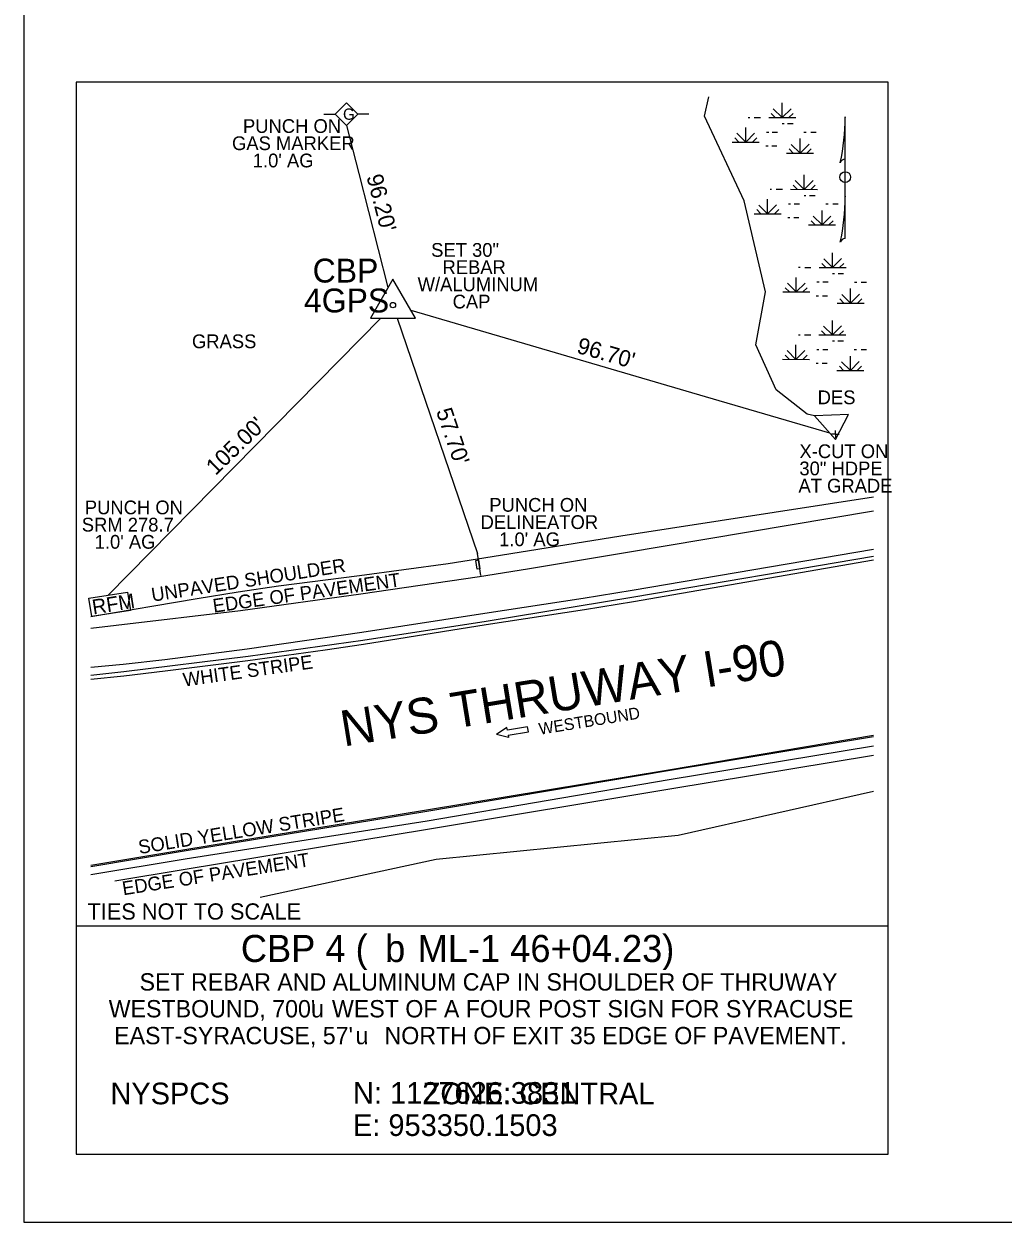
# Model space of a CAD drawing. Extents: x 953375 to 953970, y 1125154 to 1125656.
# Drawn here: x 953374.9 to 953579.9, y 1125154 to 1125404.8 of the extents above; entities that cross this region are included whole.
import ezdxf

# ---------------------------------------------------------------- set-up
doc = ezdxf.new("R2010")
doc.units = 0
for name, color, linetype in [('CB', 7, 'Continuous'), ('CBP', 7, 'Continuous'), ('CBP_C', 7, 'Continuous'), ('CBS_C', 7, 'Continuous'), ('CBT', 7, 'Continuous'), ('Default', 7, 'Continuous'), ('DES', 7, 'Continuous'), ('DES_C', 7, 'Continuous'), ('DINV', 7, 'Continuous'), ('LUKP_C', 7, 'Continuous'), ('NNA_P', 7, 'Continuous'), ('PE', 7, 'Continuous'), ('PE_C', 7, 'Continuous'), ('PET', 7, 'Continuous'), ('PSU', 7, 'Continuous'), ('PSU_C', 7, 'Continuous'), ('RC_C', 7, 'Continuous'), ('RRS', 7, 'Continuous'), ('SDEL', 7, 'Continuous'), ('SRM', 7, 'Continuous'), ('STSEW', 7, 'Continuous'), ('STSEW_I', 7, 'Continuous'), ('STSEY', 7, 'Continuous'), ('STSEY_C', 7, 'Continuous')]:
    doc.layers.add(name, color=color, linetype=linetype)

# ---------------------------------------------------------------- blocks, each defined once
blk = doc.blocks.new('NNAM')
at = {"layer": 'NNA_P'}
for p, q in [((0, 0.0147), (0, 0.0501)), ((0, 0.0496), (0, 0.0496)), ((0, 0.0496), (0, 0.0496)), ((0, -0.0004), (0, 0.0147)), ((0, -0.0168), (0, -0.0004)), ((0, -0.0166), (0, -0.0168)), ((0, -0.0172), (0, -0.0168)), ((0, -0.0518), (0, -0.0172))]:
    blk.add_line(p, q, dxfattribs=at)
blk.add_circle((0, -0.0003), 0.00455, dxfattribs=at)
for centre, radius, start, end in [((-0.1834, 0.0501), 0.1834, 347.8839, 359.8678), ((0.1834, 0.0501), 0.1834, 179.9909, 180.1322), ((0, 0.0105), 0.00425, 90.435, 165.5809), ((-0.1834, -0.0164), 0.1834, 347.8839, 359.8678), ((0.1834, -0.0164), 0.1834, 179.9909, 180.1322), ((-0.1834, -0.0164), 0.1834, 359.9196, 0.009), ((0, -0.056), 0.00424, 90.0107, 164.1061)]:
    blk.add_arc(centre, radius, start, end, dxfattribs=at)

msp = doc.modelspace()

# ---------------------------------------------------------------- linework, layer by layer
at = {"layer": 'CB'}
msp.add_line((953385.84, 1125215.99), (953555.84, 1125215.99), dxfattribs=at)
msp.add_lwpolyline([(953555.84, 1125168.2), (953555.84, 1125392.66), (953385.84, 1125392.66), (953385.84, 1125168.2)], close=True, dxfattribs=at)
at = {"layer": 'CBP'}
for points in [[(953452.16, 1125351.43), (953447.43, 1125343.25)], [(953456.88, 1125343.25), (953452.16, 1125351.43)], [(953447.43, 1125343.25), (953456.88, 1125343.25)]]:
    msp.add_lwpolyline(points, dxfattribs=at)
msp.add_circle((953452.16, 1125345.97), 0.564, dxfattribs=at)
at = {"layer": 'CBT'}
for p, q in [((953442.42, 1125383.61), (953445.01, 1125373.56)), ((953451.12, 1125349.63), (953451.12, 1125349.63)), ((953455.95, 1125344.86), (953455.95, 1125344.86)), ((953449.65, 1125343.25), (953449.65, 1125343.25)), ((953453.06, 1125343.25), (953469.83, 1125293.99)), ((953543.64, 1125319.15), (953517.6, 1125326.79)), ((953392.55, 1125285.24), (953392.55, 1125285.24))]:
    msp.add_line(p, q, dxfattribs=at)
for points in [[(953445.01, 1125373.56), (953451.12, 1125349.63)], [(953517.6, 1125326.78), (953455.95, 1125344.86)], [(953392.55, 1125285.24), (953449.65, 1125343.25)]]:
    msp.add_lwpolyline(points, dxfattribs=at)
at = {"layer": 'Default'}
msp.add_lwpolyline([(953374.91, 1125153.95), (953970.07, 1125153.95), (953970.07, 1125655.74), (953374.91, 1125655.74)], close=True, dxfattribs=at)
at = {"layer": 'DES'}
msp.add_lwpolyline([(953540.43, 1125322.79), (953544.83, 1125317.81), (953547.52, 1125323.03), (953540.43, 1125322.79)], dxfattribs=at)
at = {"layer": 'DINV'}
for q in [(953544.01, 1125318.93), (953544.79, 1125319.72), (953545.58, 1125318.93), (953544.79, 1125318.15)]:
    msp.add_line((953544.79, 1125318.93), q, dxfattribs=at)
at = {"layer": 'PE'}
for p, q in [((953440.06, 1125385.97), (953442.41, 1125388.33)), ((953442.41, 1125388.33), (953444.78, 1125385.97)), ((953533.64, 1125385.23), (953533.64, 1125388.3)), ((953442.42, 1125383.61), (953440.06, 1125385.97)), ((953444.78, 1125385.97), (953442.42, 1125383.61)), ((953526.51, 1125385.29), (953526.86, 1125385.29)), ((953527.82, 1125385.26), (953529.1, 1125385.26)), ((953530.83, 1125385.26), (953536.48, 1125385.23)), ((953532.21, 1125385.26), (953531.36, 1125386.12)), ((953533.64, 1125385.23), (953531.8, 1125387.07)), ((953533.64, 1125385.23), (953535.52, 1125387.11)), ((953535.08, 1125385.23), (953535.95, 1125386.12)), ((953526.01, 1125380.12), (953526.01, 1125383.18)), ((953533.64, 1125383.98), (953534.05, 1125383.98)), ((953534.78, 1125383.98), (953535.94, 1125383.98)), ((953523.19, 1125380.13), (953528.85, 1125380.12)), ((953524.59, 1125380.13), (953523.72, 1125381.01)), ((953526.01, 1125380.12), (953524.17, 1125381.96)), ((953526.01, 1125380.12), (953527.87, 1125382)), ((953527.43, 1125380.12), (953528.32, 1125381.01)), ((953530.35, 1125382.22), (953530.83, 1125382.22)), ((953531.59, 1125382.22), (953532.67, 1125382.22)), ((953537.4, 1125377.78), (953537.4, 1125380.83)), ((953538.2, 1125382.21), (953538.7, 1125382.21)), ((953539.63, 1125382.18), (953540.76, 1125382.18)), ((953530.21, 1125379.31), (953530.69, 1125379.31)), ((953531.52, 1125379.31), (953532.55, 1125379.31)), ((953534.59, 1125377.79), (953540.24, 1125377.78)), ((953535.98, 1125377.79), (953535.12, 1125378.67)), ((953537.4, 1125377.78), (953535.56, 1125379.62)), ((953537.4, 1125377.78), (953539.27, 1125379.66)), ((953538.82, 1125377.78), (953539.71, 1125378.67)), ((953538.24, 1125370.21), (953538.24, 1125373.27)), ((953531.11, 1125370.26), (953531.45, 1125370.26)), ((953532.42, 1125370.23), (953533.7, 1125370.23)), ((953535.42, 1125370.23), (953541.08, 1125370.21)), ((953536.8, 1125370.23), (953535.95, 1125371.1)), ((953538.24, 1125370.21), (953536.4, 1125372.05)), ((953538.24, 1125370.21), (953540.12, 1125372.09)), ((953539.67, 1125370.21), (953540.55, 1125371.1)), ((953530.6, 1125365.09), (953530.6, 1125368.16)), ((953538.24, 1125368.95), (953538.64, 1125368.95)), ((953539.38, 1125368.95), (953540.54, 1125368.95)), ((953527.79, 1125365.11), (953533.45, 1125365.09)), ((953529.18, 1125365.11), (953528.32, 1125365.99)), ((953530.6, 1125365.09), (953528.77, 1125366.93)), ((953530.6, 1125365.09), (953532.47, 1125366.97)), ((953532.03, 1125365.09), (953532.92, 1125365.99)), ((953534.95, 1125367.2), (953535.42, 1125367.2)), ((953536.19, 1125367.2), (953537.26, 1125367.2)), ((953542, 1125362.75), (953542, 1125365.8)), ((953542.79, 1125367.18), (953543.29, 1125367.18)), ((953544.23, 1125367.16), (953545.36, 1125367.16)), ((953534.81, 1125364.29), (953535.29, 1125364.29)), ((953536.12, 1125364.29), (953537.15, 1125364.29)), ((953539.19, 1125362.77), (953544.84, 1125362.75)), ((953540.58, 1125362.77), (953539.71, 1125363.65)), ((953542, 1125362.75), (953540.16, 1125364.59)), ((953542, 1125362.75), (953543.87, 1125364.63)), ((953543.42, 1125362.75), (953544.31, 1125363.65)), ((953544.22, 1125353.83), (953542.38, 1125355.67)), ((953544.22, 1125353.83), (953544.22, 1125356.9)), ((953544.22, 1125353.83), (953546.1, 1125355.71)), ((953537.09, 1125353.89), (953537.44, 1125353.89)), ((953538.4, 1125353.86), (953539.68, 1125353.86)), ((953541.41, 1125353.86), (953547.06, 1125353.83)), ((953542.79, 1125353.86), (953541.94, 1125354.72)), ((953544.22, 1125352.58), (953544.63, 1125352.58)), ((953545.36, 1125352.58), (953546.52, 1125352.58)), ((953545.66, 1125353.83), (953546.53, 1125354.72)), ((953536.59, 1125348.72), (953534.75, 1125350.56)), ((953536.59, 1125348.72), (953536.59, 1125351.78)), ((953536.59, 1125348.72), (953538.46, 1125350.6)), ((953540.93, 1125350.82), (953541.41, 1125350.82)), ((953542.17, 1125350.82), (953543.25, 1125350.82)), ((953548.78, 1125350.81), (953549.28, 1125350.81)), ((953550.21, 1125350.78), (953551.34, 1125350.78)), ((953533.77, 1125348.73), (953539.43, 1125348.72)), ((953535.17, 1125348.73), (953534.3, 1125349.61)), ((953538.01, 1125348.72), (953538.9, 1125349.61)), ((953540.8, 1125347.91), (953541.27, 1125347.91)), ((953542.1, 1125347.91), (953543.14, 1125347.91)), ((953547.98, 1125346.38), (953546.14, 1125348.22)), ((953547.98, 1125346.38), (953547.98, 1125349.43)), ((953547.98, 1125346.38), (953549.85, 1125348.26)), ((953545.17, 1125346.39), (953550.82, 1125346.38)), ((953546.56, 1125346.39), (953545.7, 1125347.27)), ((953549.4, 1125346.38), (953550.3, 1125347.27)), ((953544.17, 1125339.72), (953544.17, 1125342.78)), ((953542.74, 1125339.74), (953541.89, 1125340.61)), ((953544.17, 1125339.72), (953542.33, 1125341.55)), ((953544.17, 1125339.72), (953546.05, 1125341.6)), ((953545.61, 1125339.72), (953546.49, 1125340.61)), ((953536.54, 1125334.6), (953536.54, 1125337.67)), ((953537.04, 1125339.77), (953537.39, 1125339.77)), ((953538.35, 1125339.74), (953539.63, 1125339.74)), ((953541.36, 1125339.74), (953547.01, 1125339.72)), ((953544.17, 1125338.46), (953544.58, 1125338.46)), ((953545.32, 1125338.46), (953546.47, 1125338.46)), ((953535.12, 1125334.62), (953534.26, 1125335.5)), ((953536.54, 1125334.6), (953534.7, 1125336.44)), ((953536.54, 1125334.6), (953538.41, 1125336.48)), ((953537.96, 1125334.6), (953538.85, 1125335.5)), ((953540.89, 1125336.71), (953541.36, 1125336.71)), ((953542.13, 1125336.71), (953543.2, 1125336.71)), ((953547.93, 1125332.26), (953547.93, 1125335.31)), ((953548.73, 1125336.69), (953549.23, 1125336.69)), ((953550.16, 1125336.67), (953551.29, 1125336.67)), ((953533.73, 1125334.62), (953539.38, 1125334.6)), ((953540.75, 1125333.8), (953541.22, 1125333.8)), ((953542.06, 1125333.8), (953543.09, 1125333.8)), ((953546.51, 1125332.28), (953545.65, 1125333.16)), ((953547.93, 1125332.26), (953546.1, 1125334.1)), ((953547.93, 1125332.26), (953549.8, 1125334.14)), ((953549.35, 1125332.26), (953550.25, 1125333.16)), ((953545.12, 1125332.28), (953550.78, 1125332.26))]:
    msp.add_line(p, q, dxfattribs=at)
for points in [[(953540.43, 1125322.79), (953538.91, 1125323.1), (953532.36, 1125328.2), (953528.17, 1125337.66), (953530.17, 1125348.77), (953525.72, 1125367.84), (953517.41, 1125385.57), (953518.28, 1125389.61)], [(953437.7, 1125385.97), (953440.06, 1125385.97)], [(953447.14, 1125385.97), (953444.78, 1125385.97)], [(953547.57, 1125323.04), (953547.52, 1125323.03)], [(953552.77, 1125302.79), (953500.43, 1125294.01), (953480.33, 1125290.66), (953470.27, 1125289.07), (953445.43, 1125285.46), (953420.27, 1125281.98), (953394.19, 1125278.85), (953388.92, 1125278.26)], [(953393.96, 1125225.38), (953408.64, 1125227.82), (953459.36, 1125236.23), (953510.15, 1125244.66), (953552.77, 1125251.74)]]:
    msp.add_lwpolyline(points, dxfattribs=at)
at = {"layer": 'PET'}
for points in [[(953552.77, 1125293.34), (953502.59, 1125284.81), (953471.67, 1125279.75), (953445.84, 1125275.73), (953421.87, 1125272.4), (953395.84, 1125269.16), (953388.92, 1125268.42)], [(953388.92, 1125228.39), (953408.44, 1125231.7), (953458.82, 1125239.91), (953509.79, 1125248.51), (953552.77, 1125255.63)]]:
    msp.add_lwpolyline(points, dxfattribs=at)
at = {"layer": 'PSU'}
for points in [[(953552.77, 1125305.74), (953499.84, 1125297.62), (953472.93, 1125293.23), (953463.7, 1125291.82), (953445.19, 1125289.28), (953428.23, 1125287.09), (953419.77, 1125285.87), (953411.2, 1125284.46), (953388.92, 1125280.68)], [(953424.35, 1125222.01), (953461.19, 1125229.97), (953511.9, 1125234.99), (953552.77, 1125244.16)]]:
    msp.add_lwpolyline(points, dxfattribs=at)
at = {"layer": 'RC_C'}
for p, q in [((953476.02, 1125257.52), (953473.83, 1125256.07)), ((953476.11, 1125256.98), (953476.02, 1125257.52)), ((953480.36, 1125257.68), (953476.11, 1125256.98)), ((953480.53, 1125256.62), (953480.36, 1125257.68)), ((953476.37, 1125255.39), (953473.83, 1125256.07)), ((953476.28, 1125255.93), (953480.53, 1125256.62)), ((953476.28, 1125255.93), (953476.37, 1125255.39))]:
    msp.add_line(p, q, dxfattribs=at)
at = {"layer": 'RRS'}
for points in [[(953552.77, 1125294.81), (953502.22, 1125286.18), (953491.97, 1125284.5), (953471.42, 1125281.36), (953445.63, 1125277.39), (953421.64, 1125273.95), (953404.37, 1125271.69), (953395.71, 1125270.72), (953388.92, 1125270.06)], [(953388.92, 1125226.73), (953408.63, 1125230.03), (953459.34, 1125238), (953510.02, 1125246.62), (953552.77, 1125253.66)]]:
    msp.add_lwpolyline(points, dxfattribs=at)
at = {"layer": 'SDEL'}
msp.add_line((953470.57, 1125289.37), (953469.83, 1125293.99), dxfattribs=at)
msp.add_lwpolyline([(953470.05, 1125292.61), (953470.35, 1125290.75), (953469.79, 1125290.65), (953469.49, 1125292.52)], close=True, dxfattribs=at)
at = {"layer": 'SRM'}
msp.add_lwpolyline([(953388.52, 1125284.6), (953396.59, 1125285.87), (953397.19, 1125282.04), (953389.12, 1125280.77)], close=True, dxfattribs=at)
at = {"layer": 'STSEW'}
msp.add_lwpolyline([(953552.77, 1125292.53), (953502.55, 1125283.85), (953492.28, 1125282.17), (953471.69, 1125279.01), (953446.01, 1125274.91), (953437.94, 1125273.72), (953421.79, 1125271.5), (953404.5, 1125269.3), (953395.84, 1125268.29), (953388.92, 1125267.56)], dxfattribs=at)
at = {"layer": 'STSEY'}
msp.add_lwpolyline([(953388.92, 1125228.71), (953408.56, 1125231.95), (953458.79, 1125240.21), (953509.87, 1125248.64), (953552.77, 1125255.92)], dxfattribs=at)

# ---------------------------------------------------------------- block references
at = {"layer": 'Default', "xscale": 250, "yscale": 250}
msp.add_blockref('NNAM', (953546.85, 1125372.85), dxfattribs=at)

# ---------------------------------------------------------------- texts
at = {"layer": 'CBP_C'}
for s, height, rotation, p in [("96.20'", 3.402, 284.6048, (953446.59, 1125372.9)), ("96.70'", 3.402, 343.9823, (953490.45, 1125336.02)), ("105.00'", 3.402, 43.9686, (953415.03, 1125310.18)), ("57.70'", 3.402, 288.7394, (953461.15, 1125323.78)), ('TIES NOT TO SCALE', 3.4016, 359.9999, (953388.21, 1125217.29))]:
    msp.add_text(s, height=height, rotation=rotation, dxfattribs=at).set_placement(p)
for s, height, p in [('CBP', 5.002, (953435.35, 1125350.7)), ('4GPS', 5.002, (953433.53, 1125344.44)), ('CBP 4 (', 5.669, (953420.32, 1125208.41)), ('b', 5.67, (953450.52, 1125208.41)), (' ML-1 46+04.23)', 5.6693, (953455.23, 1125208.41)), ('SET REBAR AND ALUMINUM CAP IN SHOULDER OF THRUWAY ', 3.6284, (953399.11, 1125202.43)), ("WESTBOUND, 700'", 3.6284, (953392.65, 1125196.81)), ('u', 3.63, (953435, 1125196.81)), (' WEST OF A FOUR POST SIGN FOR SYRACUSE', 3.6284, (953438.04, 1125196.81)), ("EAST-SYRACUSE, 57'", 3.6284, (953393.79, 1125191.19)), ('NORTH OF EXIT 35 EDGE OF PAVEMENT.', 3.6284, (953450.4, 1125191.19)), ('u ', 3.628, (953444.33, 1125191.19)), ('NYSPCS                        ZONE: CENTRAL', 4.5355, (953393.01, 1125178.61)), ('N: 1127626.3831', 4.5355, (953443.8, 1125178.72)), ('E: 953350.1503', 4.5355, (953443.8, 1125171.98))]:
    msp.add_text(s, height=height, dxfattribs=at).set_placement(p)
at = {"layer": 'CBS_C'}
for s, p in [('PUNCH ON', (953420.76, 1125382.03)), ('GAS MARKER', (953418.47, 1125378.43)), ("1.0' AG", (953422.81, 1125374.82)), ('SET 30" ', (953460.16, 1125356.09)), ('REBAR', (953462.53, 1125352.48)), ('W/ALUMINUM ', (953457.33, 1125348.88)), ('CAP', (953464.66, 1125345.27)), ('X-CUT ON ', (953537.27, 1125313.93)), ('30" HDPE', (953537.26, 1125310.33)), ('AT GRADE', (953537.06, 1125306.72)), ('PUNCH ON ', (953387.65, 1125302.17)), ('PUNCH ON ', (953472.33, 1125302.7)), ('SRM 278.7', (953387.01, 1125298.56)), ('DELINEATOR', (953470.51, 1125299.09)), ("1.0' AG", (953389.71, 1125294.96)), ("1.0' AG", (953474.39, 1125295.49))]:
    msp.add_text(s, height=2.88, dxfattribs=at).set_placement(p)
at = {"layer": 'DES_C'}
msp.add_text('DES', height=2.88, dxfattribs=at).set_placement((953541.08, 1125325.22))
at = {"layer": 'LUKP_C'}
msp.add_text('GRASS', height=2.88, dxfattribs=at).set_placement((953410.08, 1125336.95))
at = {"layer": 'PE'}
msp.add_text('G', height=2.36, rotation=0, dxfattribs=at).set_placement((953441.71, 1125384.79))
at = {"layer": 'PE_C'}
for rotation, p in [(8.0438, (953414.65, 1125281.54)), (8.8531, (953395.71, 1125222.37))]:
    msp.add_text('EDGE OF PAVEMENT', height=2.88, rotation=rotation, dxfattribs=at).set_placement(p)
at = {"layer": 'PSU_C'}
msp.add_text(' UNPAVED SHOULDER', height=2.88, rotation=8.7751, dxfattribs=at).set_placement((953400.75, 1125283.69))
at = {"layer": 'RC_C'}
for s, height, p in [('NYS THRUWAY I-90', 7.5024, (953441.84, 1125253.51)), ('WESTBOUND', 2.461, (953482.92, 1125255.98))]:
    msp.add_text(s, height=height, rotation=9.2515, dxfattribs=at).set_placement(p)
at = {"layer": 'SRM'}
msp.add_text('RFM', height=3.099, rotation=8.919, dxfattribs=at).set_placement((953389.43, 1125281.18))
at = {"layer": 'STSEW_I'}
msp.add_text('WHITE STRIPE', height=2.88, rotation=8.0364, dxfattribs=at).set_placement((953408.42, 1125266.07))
at = {"layer": 'STSEY_C'}
msp.add_text('SOLID YELLOW STRIPE', height=2.88, rotation=9.1413, dxfattribs=at).set_placement((953399.09, 1125231.01))

doc.saveas('drawing.dxf')
